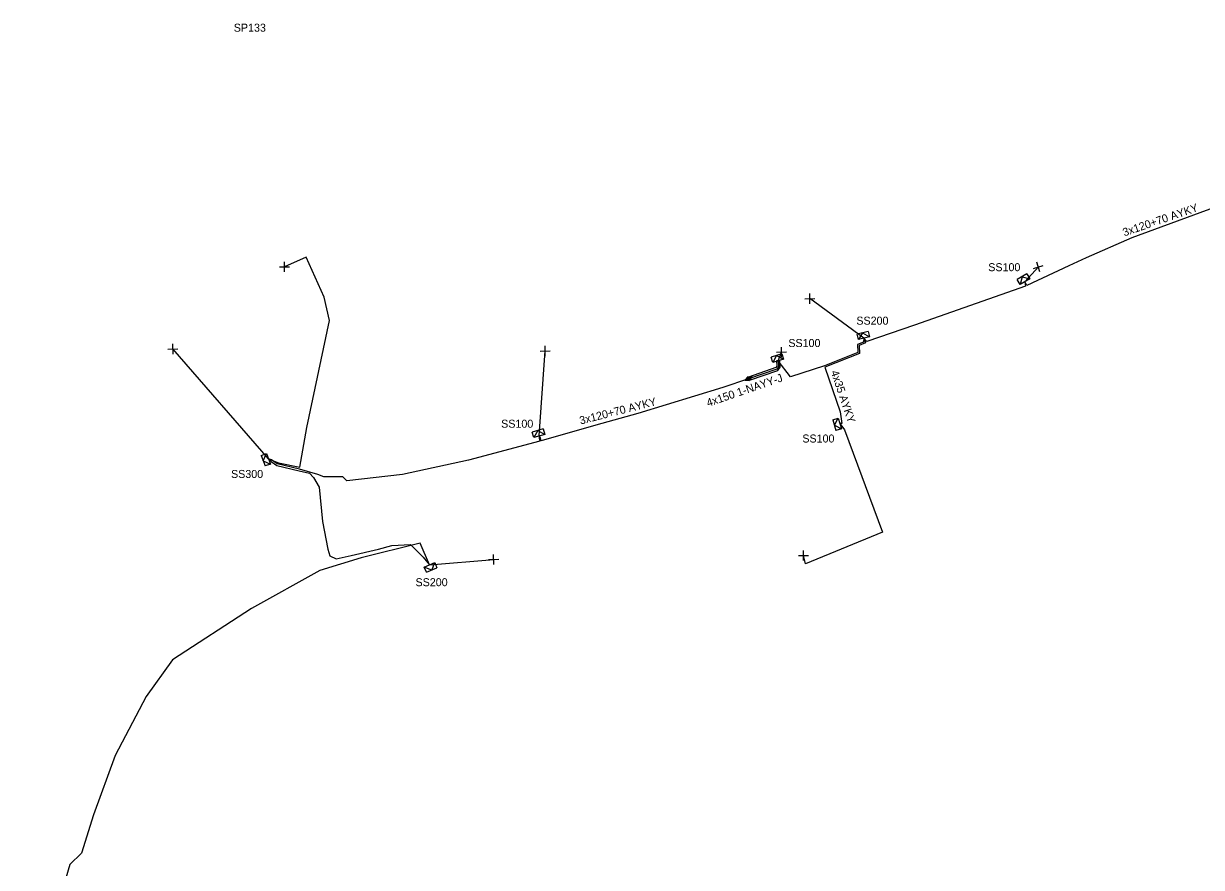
# Model space of a CAD drawing. Extents: x -762504 to -761250, y -1152974 to -1152253.
# Drawn here: x -761801.7 to -761655.3, y -1152553 to -1152448.2 of the extents above; entities that cross this region are included whole.
import ezdxf

# ---------------------------------------------------------------- set-up
doc = ezdxf.new("R2010")
doc.units = 0
for name, color, linetype in [('Vrstva 19', 7, 'Continuous'), ('Vrstva 20', 7, 'Continuous'), ('Vrstva 31', 7, 'Continuous'), ('Vrstva 33', 7, 'Continuous'), ('Vrstva 34', 7, 'Continuous'), ('Vrstva 5', 7, 'Continuous'), ('Vrstva 52', 7, 'Continuous'), ('Vrstva 54', 7, 'Continuous'), ('Vrstva 59', 7, 'Continuous'), ('Vrstva 6', 7, 'Continuous')]:
    doc.layers.add(name, color=color, linetype=linetype)

msp = doc.modelspace()

# ---------------------------------------------------------------- linework, layer by layer
at = {"layer": 'Vrstva 19'}
for points in [[(-761711.525, -1152492.563), (-761711.156, -1152492.142), (-761711.713, -1152492.099), (-761712.083, -1152492.516), (-761711.525, -1152492.563)], [(-761711.275, -1152492.194), (-761711.689, -1152492.157), (-761711.955, -1152492.465), (-761711.549, -1152492.504), (-761711.275, -1152492.194)], [(-761711.392, -1152492.241), (-761711.665, -1152492.216), (-761711.852, -1152492.427), (-761711.572, -1152492.446), (-761711.392, -1152492.241)], [(-761711.505, -1152492.287), (-761711.642, -1152492.274), (-761711.739, -1152492.381), (-761711.596, -1152492.387), (-761711.505, -1152492.287)]]:
    msp.add_lwpolyline(points, dxfattribs=at)
at = {"layer": 'Vrstva 20'}
msp.add_lwpolyline([(-761708.13, -1152490.11), (-761708.08, -1152490.75), (-761708.23, -1152490.95), (-761711.63, -1152492.12), (-761711.5, -1152492.5), (-761707.97, -1152491.29), (-761707.68, -1152490.87), (-761707.73, -1152490.09)], close=True, dxfattribs=at)
at = {"layer": 'Vrstva 31'}
for points in [[(-761677.021, -1152479.312), (-761678.234, -1152480.012)], [(-761677.021, -1152479.312), (-761676.671, -1152479.918), (-761677.884, -1152480.618), (-761678.234, -1152480.012)], [(-761677.628, -1152479.662), (-761677.884, -1152480.618)], [(-761677.628, -1152479.662), (-761676.671, -1152479.918)], [(-761696.753, -1152486.459), (-761698.117, -1152486.774)], [(-761696.753, -1152486.459), (-761696.595, -1152487.142), (-761697.959, -1152487.456), (-761698.117, -1152486.774)], [(-761697.435, -1152486.617), (-761697.959, -1152487.456)], [(-761697.435, -1152486.617), (-761696.595, -1152487.142)], [(-761707.478, -1152489.216), (-761708.81, -1152489.649)], [(-761707.478, -1152489.216), (-761707.262, -1152489.882), (-761708.593, -1152490.315), (-761708.81, -1152489.649)], [(-761708.144, -1152489.433), (-761708.593, -1152490.315)], [(-761708.144, -1152489.433), (-761707.262, -1152489.882)], [(-761701.137, -1152497.417), (-761700.465, -1152497.224), (-761700.079, -1152498.57), (-761700.752, -1152498.763)], [(-761701.137, -1152497.417), (-761700.752, -1152498.763)], [(-761700.945, -1152498.09), (-761700.465, -1152497.224)], [(-761700.945, -1152498.09), (-761700.079, -1152498.57)], [(-761737.137, -1152498.563), (-761738.483, -1152498.949)], [(-761737.137, -1152498.563), (-761736.944, -1152499.236), (-761738.29, -1152499.622), (-761738.483, -1152498.949)], [(-761737.81, -1152498.756), (-761738.29, -1152499.622)], [(-761737.81, -1152498.756), (-761736.944, -1152499.236)], [(-761772.149, -1152501.849), (-761771.491, -1152501.61), (-761771.012, -1152502.925), (-761771.67, -1152503.165)], [(-761772.149, -1152501.849), (-761771.67, -1152503.165)], [(-761771.909, -1152502.507), (-761771.491, -1152501.61)], [(-761771.909, -1152502.507), (-761771.012, -1152502.925)], [(-761751.623, -1152516.359), (-761751.897, -1152515.715), (-761750.608, -1152515.168), (-761750.335, -1152515.812)], [(-761750.979, -1152516.086), (-761751.897, -1152515.715)], [(-761751.623, -1152516.359), (-761750.335, -1152515.812)], [(-761750.979, -1152516.086), (-761750.608, -1152515.168)]]:
    msp.add_lwpolyline(points, dxfattribs=at)
at = {"layer": 'Vrstva 34'}
for points in [[(-761769.895, -1152478.441), (-761768.645, -1152478.419)], [(-761769.259, -1152479.055), (-761769.281, -1152477.805)], [(-761676.195, -1152478.633), (-761675.006, -1152478.246)], [(-761675.407, -1152479.034), (-761675.793, -1152477.845)], [(-761703.989, -1152483.005), (-761704.011, -1152481.755)], [(-761704.625, -1152482.391), (-761703.375, -1152482.369)], [(-761783.119, -1152489.255), (-761783.141, -1152488.005)], [(-761783.755, -1152488.641), (-761782.505, -1152488.619)], [(-761737.505, -1152488.891), (-761736.255, -1152488.869)], [(-761736.869, -1152489.505), (-761736.891, -1152488.255)], [(-761708.145, -1152489.021), (-761706.895, -1152488.999)], [(-761707.509, -1152489.635), (-761707.531, -1152488.385)], [(-761743.269, -1152515.395), (-761743.291, -1152514.145)], [(-761705.415, -1152514.291), (-761704.165, -1152514.269)], [(-761704.779, -1152514.905), (-761704.801, -1152513.655)], [(-761743.905, -1152514.781), (-761742.655, -1152514.759)]]:
    msp.add_lwpolyline(points, dxfattribs=at)
at = {"layer": 'Vrstva 5'}
for points in [[(-761641.29, -1152466.27), (-761641.1, -1152466.87), (-761641.67, -1152467.01), (-761646, -1152468.58), (-761653.53, -1152470.98), (-761663.99, -1152474.81), (-761669.68, -1152477.3), (-761671.82, -1152478.31), (-761677.04, -1152480.76), (-761677.28, -1152480.27), (-761677.22, -1152480.83), (-761690.99, -1152485.68), (-761696.92, -1152487.72), (-761697.28, -1152487.3), (-761697.33, -1152487.77), (-761698.06, -1152488.07), (-761698.03, -1152489.06), (-761702.19, -1152490.71), (-761706.38, -1152492.07), (-761707.93, -1152490.1)], [(-761707.93, -1152490.1), (-761707.88, -1152490.81), (-761708.1, -1152491.12), (-761711.62, -1152492.33)], [(-761711.62, -1152492.33), (-761714.79, -1152493.42), (-761725.37, -1152496.66), (-761730.59, -1152498.11), (-761737.36, -1152500.02), (-761737.45, -1152499.68), (-761737.62, -1152499.43), (-761737.64, -1152499.74), (-761737.56, -1152500.08), (-761746.39, -1152502.44), (-761754.59, -1152504.22), (-761761.52, -1152505), (-761762.01, -1152504.5), (-761764.39, -1152504.53), (-761765.14, -1152504.23), (-761767.4, -1152503.55), (-761770.16, -1152502.91), (-761770.9, -1152502.4), (-761771.25, -1152502.27)], [(-761771.25, -1152502.27), (-761770.93, -1152502.62), (-761770.24, -1152503.09), (-761767.45, -1152503.75), (-761766.18, -1152504.07), (-761765.66, -1152504.58), (-761764.97, -1152505.8), (-761764.56, -1152510.05), (-761763.89, -1152513.5), (-761763.64, -1152514.33), (-761762.83, -1152514.71), (-761760.99, -1152514.3), (-761757.58, -1152513.5), (-761755.92, -1152513.06), (-761753.61, -1152512.91), (-761752.03, -1152514.51), (-761751.25, -1152515.44)]]:
    msp.add_lwpolyline(points, dxfattribs=at)
at = {"layer": 'Vrstva 52'}
for points in [[(-761697.28, -1152487.3), (-761697.08, -1152487.88), (-761697.86, -1152488.21), (-761697.83, -1152489.2), (-761702.12, -1152490.9), (-761700.22, -1152496.43), (-761700.01, -1152497.88), (-761700.27, -1152497.9)], [(-761751.25, -1152515.44), (-761752.43, -1152512.76), (-761759.76, -1152514.56), (-761764.88, -1152516.14), (-761773.35, -1152520.87), (-761783.17, -1152527.25), (-761786.46, -1152531.8), (-761790.31, -1152539.13), (-761792.98, -1152546.51), (-761794.5, -1152551.26), (-761795.93, -1152552.67), (-761798.92, -1152562.83), (-761801.69, -1152574.76), (-761799.48, -1152575.58)]]:
    msp.add_lwpolyline(points, dxfattribs=at)
at = {"layer": 'Vrstva 59'}
for points in [[(-761771.25, -1152502.27), (-761770.03, -1152502.77), (-761767.36, -1152503.31), (-761766.48, -1152498.38), (-761763.69, -1152485.09), (-761764.35, -1152482.2), (-761766.58, -1152477.21), (-761769.27, -1152478.43)], [(-761677.28, -1152480.27), (-761675.6, -1152478.44)], [(-761697.28, -1152487.3), (-761704, -1152482.38)], [(-761771.25, -1152502.27), (-761783.13, -1152488.63)], [(-761737.62, -1152499.43), (-761736.88, -1152488.88)], [(-761707.93, -1152490.1), (-761707.52, -1152489.01)], [(-761700.27, -1152497.9), (-761699.71, -1152498.69), (-761694.98, -1152511.37), (-761704.54, -1152515.33), (-761704.79, -1152514.28)], [(-761751.25, -1152515.44), (-761743.28, -1152514.77)]]:
    msp.add_lwpolyline(points, dxfattribs=at)

# ---------------------------------------------------------------- texts
at = {"layer": 'Vrstva 33'}
for s, p in [('SP133', (-761775.57, -1152449.22)), ('SS100', (-761681.83, -1152478.97)), ('SS200', (-761698.22, -1152485.61)), ('SS100', (-761706.67, -1152488.39)), ('SS100', (-761742.35, -1152498.41)), ('SS100', (-761704.93, -1152500.25)), ('SS300', (-761775.91, -1152504.65)), ('SS200', (-761752.99, -1152518.1))]:
    msp.add_text(s, height=0.9943, dxfattribs=at).set_placement(p)
at = {"layer": 'Vrstva 54'}
msp.add_text('4x35 AYKY', height=0.9943, rotation=288.66305, dxfattribs=at).set_placement((-761701.41, -1152491.47))
at = {"layer": 'Vrstva 6'}
for s, rotation, p in [('3x120+70 AYKY', 18.95648, (-761664.93, -1152474.66)), ('4x150 1-NAYY-J', 18.97041, (-761716.64, -1152495.83)), ('3x120+70 AYKY', 14.33393, (-761732.48, -1152498.02))]:
    msp.add_text(s, height=0.99429, rotation=rotation, dxfattribs=at).set_placement(p)

doc.saveas('drawing.dxf')
